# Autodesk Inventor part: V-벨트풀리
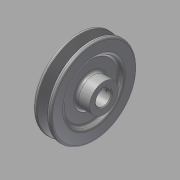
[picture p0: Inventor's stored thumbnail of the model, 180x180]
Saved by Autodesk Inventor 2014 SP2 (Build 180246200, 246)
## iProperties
Created: 2015-09
Part Number: V-벨트풀리
Material: 강철, 연강
Document SubType Name: Modeling
Designer: mduedu
Density: 1 g/cm^3
Appearance: 강철
Author: mduedu
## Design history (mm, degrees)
sketch "스케치1"
  geometry: L1 (-10, 0)-(10, 0); L2 (-10, 0)-(-10, 48); L3 (-10, 48)-(-5.976, 48); L4 (-5.976, 48)-(-2.154, 35.5); L5 (-2.154, 35.5)-(2.154, 35.5); L6 (2.154, 35.5)-(5.976, 48); L7 (5.976, 48)-(10, 48); L8 (10, 48)-(10, 0); L9 (0, 0)-(0, 35.5); L10 (-10, 43.5)-(10, 43.5); 3 further points
  constraints: 20 end point, 6 point on line, 3 perpendicular, 2 midpoint, 2 parallel, 2 symmetric about line, 1 coincident, 1 collinear, 1 equal length, 1 horizontal, 1 vertical, 1 vertical alignment
  dimensions: "d0" = 20 distance between parallel lines of L8 L2; "d2" = 96 diameter of L3 L1; "d3" = 87 diameter of L10 L1; "d4" = 4.5 distance between parallel lines of L10 L3 (derived); "d5" = 8 distance between parallel lines of L5 L10; "d6" = 9.2 distance of point (4.6, 43.5) point (-4.6, 43.5); "d7" = 34 deg angle of L6 L4
revolve "회전1" sketch "스케치1" stored, may be unused: angle "d8" = 90 deg
sketch "스케치2"
  geometry: C1 r 16 at (0, 0); 1 further point
  constraints: 1 centre point, 1 coincident
  dimensions: "d9" = 32 diameter of C1
extrude "돌출1" join sketch "스케치2" distance "d10" = 11; taper "d11" = 0 deg
fillet "모깎기1" dims "d12" = 1, "d13" = 0.5, "d14" = 2
sketch "스케치3"
  geometry: C1 r 16 at (0, 0) reference; C2 r 32 at (0, 0); 1 further point
  constraints: 1 centre point, 1 coincident
  dimensions: "d15" = 64 diameter of C2
extrude "돌출2" cut sketch "스케치3" distance "d16" = 4; taper "d17" = 0 deg
fillet "모깎기2" dims "d18" = 3
fillet "모깎기3" dims "d19" = 3
fillet "모깎기4" dims "d20" = 3
sketch "스케치4"
  geometry: C1 r 8.5 at (0, 0); 1 further point
  constraints: 1 centre point, 1 coincident
  dimensions: "d21" = 17 diameter of C1
extrude "돌출3" cut sketch "스케치4" stored distance "d22" = 4; taper "d23" = 0 deg
sketch "스케치5"
  geometry: L1 (-2.5, 8.124)-(2.5, 8.124); L2 (2.5, 8.124)-(2.5, 10.8); L3 (2.5, 10.8)-(-2.5, 10.8); L4 (-2.5, 10.8)-(-2.5, 8.124); A1 r 8.5 centre (0, 0) between (-2.5, 8.124) and (2.5, 8.124) reference; 2 further points
  constraints: 8 end point, 3 point on circle, 2 parallel, 1 horizontal, 1 perpendicular, 1 vertical alignment
  dimensions: "d24" = 5 distance of L2.end L3.end; "d26" = 19.3 distance from line of L3 point (0, -8.5)
extrude "돌출4" cut sketch "스케치5" stored distance "d27" = 4; taper "d28" = 0 deg
chamfer "모따기1" distance "d29" = 1; stored, may be unused: second distance "d30" = 2, angle "d31" = 45 deg
node "작업 평면1"
sketch "스케치6"
  geometry: L1 (-11, 16)-(-11, -16) reference; 2 further points
  constraints: 1 horizontal alignment
  dimensions: "d32" = 5 distance from line of point (-6, 0) L1
hole "구멍1" sketch "스케치6" at (-6, 0) diameter "d33" = 3.242; stored, may be unused: countersink angle "d37" = 90 deg, drill point angle "d39" = 118 deg; dims "d34" = 6, "d35" = 4, "d36" = 2, "d38" = 8
node "솔리드1"
mirror "대칭1"
